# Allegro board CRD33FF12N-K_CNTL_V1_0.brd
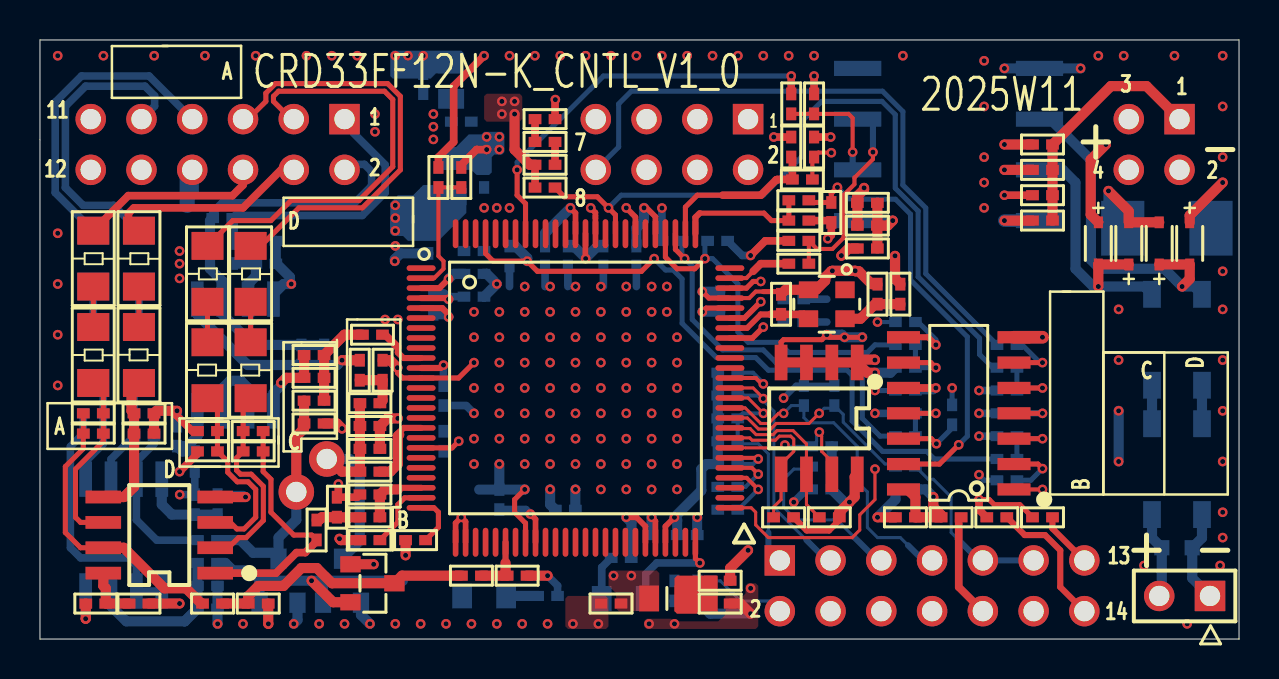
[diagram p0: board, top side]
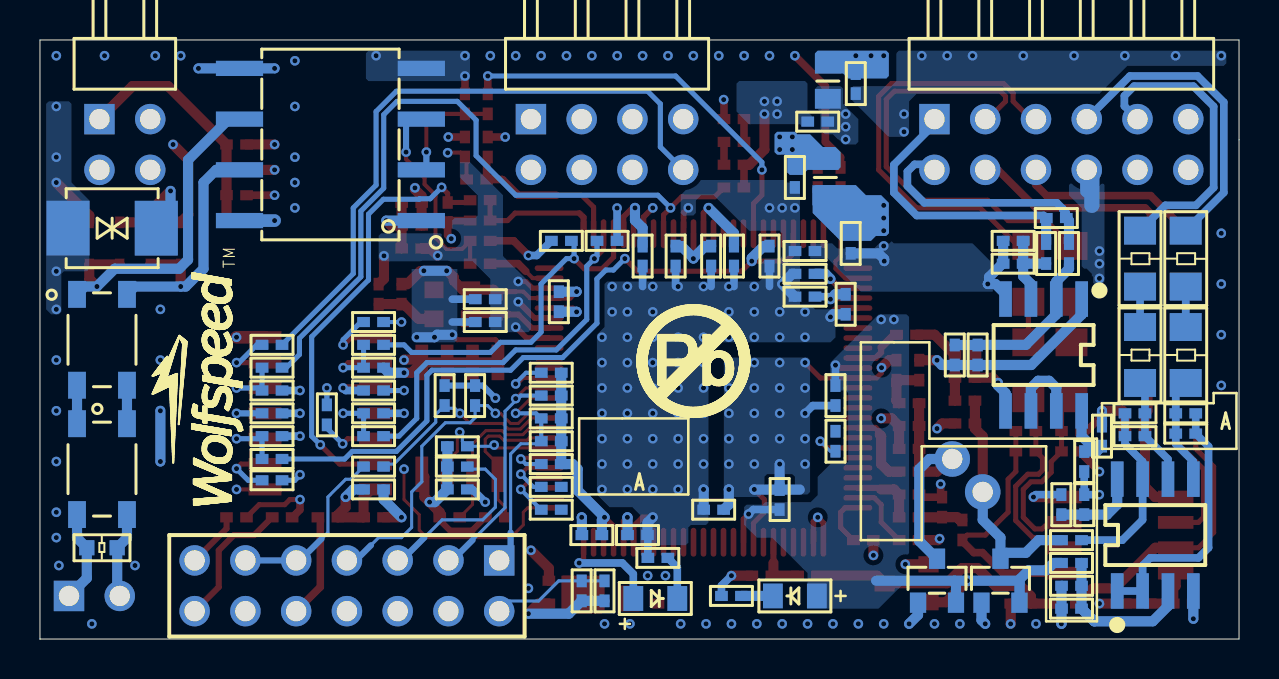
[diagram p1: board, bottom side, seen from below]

Outline 60 x 30 mm; copper layers: TOP, POWER02, GND03, BOTTOM. Coordinates in mm from the lower left corner of the outline.
Outline path: 0,30 60,30 60,0 0,0 0,30

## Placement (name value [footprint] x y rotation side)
C1  2.2u  [C0402]  37.72 17.02 180 bottom
C2  0.1u  [C0402]  32.89 2.41 90 bottom
C3  2.2u  [C0402]  41.91 17.27 90 top
C4  22p  [C0402]  37.08 16.76 90 top
C5  22n  [C0402]  19.94 23.11 90 top
C6  10u  [C0402]  26.42 19.18 90 bottom
C7  10u  [C0402]  21.72 17.14 180 bottom
C8  0.1u  [C0402]  28.19 19.18 90 bottom
C9  0.1u  [C0402]  34.04 16.89 270 bottom
C10  0.1u  [C0402]  30.1 5.21 0 bottom
C11  0.1u  [C0402]  19.68 16.76 90 bottom
C12  2.2u  [C0402]  20.19 12.19 270 bottom
C13  2.2u  [C0402]  22.99 6.99 90 bottom
C14  0.1u  [C0402]  21.72 18.29 0 bottom
C15  0.1u  [C0402]  32.38 5.21 0 bottom
C16  0.1u  [C0402]  37.72 15.88 0 bottom
C17  0.1u  [C0402]  25.27 19.18 270 bottom
C18  0.1u  [C0402]  29.84 19.18 270 bottom
C19  10u  [C0402]  19.43 19.81 270 bottom
C20  10u  [C0402]  22.23 23.11 270 bottom
C21  0.1n  [C0402]  39.6 21.36 270 top
C22  0.1n  [C0402]  38.73 24.64 90 top
C23  0.1u  [C0402]  39.12 7.49 180 bottom
C24  2.2n  [C0402]  16.51 7.24 180 top
C25  0.01u  [C0402]  14.22 14.22 90 bottom
C26  2.2n  [C0402]  17.14 13.46 90 top
C27  2.2n  [C0402]  10.67 10.41 180 top
C28  10u  [C0402]  28.57 1.78 180 top
C29  10u  [C0402]  34.04 1.78 0 top
C30  0.01u  [C0402]  11.3 18.8 180 bottom
C31  2.2n  [C0402]  14.86 6.6 90 top
C32  10u  [C0402]  19.18 27.81 270 bottom
C33  0.1u  [C0402]  21.08 25.91 0 bottom
C34  2.2n  [C0402]  10.92 1.78 0 top
C35  0.01u  [C0402]  50.16 22.23 180 top
C36  0.1u  [C0402]  50.16 23.5 180 top
C37  0.47u  [C0402]  8.38 1.52 0 bottom
C38  1u  [C0402]  50.16 24.77 180 top
C39  0.1u  [C0402]  41.4 20.7 0 top
C40  1u  [C0402]  41.4 21.84 0 top
C41  0.1u  [C0402]  8.89 6.73 90 bottom
C45  330p  [C0402]  2.67 10.29 0 bottom
C47  330p  [C0402]  5.21 11.3 0 bottom
C48  2.2n  [C0402]  13.72 10.79 0 top
C49  0.1u  [C0402]  2.79 1.78 180 top
C50  0.1u  [C0402]  6.86 10.16 90 bottom
C51  120p  [C0402]  38.73 26.8 90 top
C52  22n  [C0402]  8.38 9.4 0 top
C54  120p  [C0402]  25.27 23.75 0 top
C55  22n  [C0402]  5.21 10.29 180 top
C56  2.2n  [C0402]  2.67 10.29 0 top
C65  0.1n  [C0402]  43.31 13.59 180 bottom
C66  0.1n  [C0402]  43.31 11.3 180 bottom
C67  0.1n  [C0402]  48.39 10.16 180 bottom
C68  0.1n  [C0402]  48.39 12.45 180 bottom
C69  1u  [C0402]  45.59 6.1 0 top
C70  0.1u  [C0402]  43.31 6.1 180 top
C71  0.01u  [C0402]  43.31 7.49 180 bottom
C72  2.2n  [C0402]  16.51 10.67 0 top
C73  2.2n  [C0402]  13.72 14.22 180 top
C74  2.2n  [C0402]  23.88 3.17 0 top
C75  2.2u  [C0402]  16.51 4.95 180 top
C76  2.2u  [C0402]  18.8 4.95 180 top
C79  120p  [C0402]  37.97 19.94 180 top
D2  LED0  [LED0805]  29.21 2.03 180 bottom
D3  LED0  [LED0805]  22.23 2.16 0 bottom
D4  BAS21WS-TP  [DIOD-SOD323-2-A_V]  54.48 19.81 90 top
D5  BAS21WS-TP  [DIOD-SOD323-2-A_V]  56.01 19.81 90 top
D6  BAS21WS-TP  [DIOD-SOD323-2-A_V]  52.96 19.81 270 top
D7  BAS21WS-TP  [DIOD-SOD323-2-A_V]  57.53 19.81 270 top
D8  SMBJ15CA  [DO214AA]  56.39 20.57 0 bottom
D13  BAV99-TP  [SOT-23-3]  16.64 2.79 270 top
D14  BAV99-TP  [SOT-23-3]  11.94 2.92 180 bottom
D18  BAV99-TP  [SOT-23-3]  15.11 2.92 180 bottom
J1  Analog Singals  [HDR2X6H-254MM-90]  8.89 24.77 180 top
J2  Digital Singals  [HDR2X4H-254MM-90]  31.62 24.77 180 top
J3  JTAG  [HDR2X7H-254MM]  44.64 2.67 0 top
J4  CAN  [HDR1X2H-254MM]  57.28 2.16 180 top
J5  2*2P 1.27mm  [HDR2X2H-254MM-90]  55.75 24.77 180 top
L1  BLM21PG221SN1D  [6-0805_L]  20.7 23.11 90 bottom
L2  BLM21PG221SN1D  [6-0805_L]  31.37 2.03 0 top
L3  BLM21PG221SN1D  [6-0805_L]  20.57 27.94 270 bottom
M1  Test point  [1P]  12.83 7.37 0 top
M2  Test point  [1P]  14.35 9.02 180 bottom
NOREF  -  []  124.59 89.92 0 top
NOREF#2  -  []  124.71 120.02 0 top
NOREF#3  -  []  124.46 30.1 0 top
NOREF#4  -  []  60 0 90 top
NOREF#5  -  []  -5 2 0 top
NOREF#6  -  []  59.94 154.69 90 top
NOREF#7  -  []  124.59 59.94 0 top
NOREF#8  -  []  0 0 0 top
NOREF#9  -  []  0 0 90 top
NOREF#10  -  []  211.28 116.3 0 top
NOREF#11  -  []  407.95 59.5 0 top
R1  0  [R0402]  31.75 2.41 90 bottom
R2  10k  [R0402]  34.42 9.91 180 bottom
R3  10  [R0402]  43.05 17.27 270 top
R4  10k  [R0402]  34.42 12.19 180 bottom
R5  0  [R0402]  39.12 8.64 0 bottom
R6  10k  [R0402]  38.23 12.19 90 bottom
R7  10k  [R0402]  21.08 23.11 90 top
R8  10k  [R0402]  39.75 12.19 90 bottom
R9  2k  [R0402]  47.88 6.1 0 top
R10  0  [R0402]  43.31 8.64 180 bottom
R11  2k  [R0402]  50.16 6.1 0 top
R12  1k  [R0402]  45.64 11.23 270 bottom
R13  2k  [R0402]  29.08 4.06 180 bottom
R14  2k  [R0402]  25.4 2.16 180 bottom
R15  0  [R0402]  26.29 6.48 180 bottom
R16  1k  [R0402]  37.97 21.97 0 top
R17  1k  [R0402]  48.39 7.95 0 bottom
R18  1k  [R0402]  38.15 23.01 0 top
R19  2k  [R0402]  37.59 24.64 270 top
R20  2k  [R0402]  37.97 20.95 180 top
R21  0  [R0402]  21.72 19.43 0 bottom
R22  2k  [R0402]  8.38 3.81 180 bottom
R23  10  [R0402]  41.4 19.56 0 top
R24  2k  [R0402]  8.38 2.67 180 bottom
R25  10  [R0402]  7.75 6.73 90 bottom
R26  0  [R0402]  50.16 20.95 180 top
R27  1k  [R0402]  16.51 6.1 180 top
R28  1k  [R0402]  37.59 26.8 270 top
R29  1k  [R0402]  37.97 18.8 0 top
R30  12k  [R0402]  10.67 9.4 0 top
R31  120  [R0603]  56.9 4.57 0 bottom
R32  0  [R1206]  10.54 18.29 90 top
R33  10k  [R0402]  2.67 11.3 180 bottom
R34  620k  [R1206]  2.67 19.05 90 bottom
R35  10k  [R1206]  2.67 14.22 90 bottom
R36  12k  [R1206]  10.54 13.46 270 top
R37  620k  [R1206]  4.95 19.05 90 bottom
R38  10k  [R1206]  4.95 14.22 90 bottom
R39  10k  [R0402]  5.21 10.16 180 bottom
R40  1k  [R0402]  8.38 4.95 180 bottom
R41  10  [R0402]  4.95 1.78 0 top
R42  10  [R0402]  7.75 8.89 270 bottom
R43  100  [R0402]  34.42 6.48 0 bottom
R44  10k  [R0402]  25.27 26.04 180 top
R45  1k  [R0402]  13.84 5.46 90 top
R46  1k  [R0402]  8.64 1.78 0 top
R47  1k  [R0402]  25.27 24.89 0 top
R48  0  [R1206]  4.95 19.05 90 top
R49  12k  [R1206]  4.95 14.22 270 top
R50  0  [R1206]  8.38 18.29 90 top
R51  12k  [R0402]  5.21 11.3 0 top
R52  12k  [R0402]  2.67 11.3 180 top
R53  0  [R1206]  2.67 19.05 90 top
R54  12k  [R1206]  2.67 14.22 90 top
R55  12k  [R1206]  8.38 13.46 270 top
R57  12k  [R0402]  8.38 10.41 180 top
R65  100  [R0402]  34.42 7.62 0 bottom
R71  1k  [R0402]  43.31 15.88 0 bottom
R72  1k  [R0402]  48.39 14.73 0 bottom
R73  1k  [R0402]  43.31 14.73 0 bottom
R74  1k  [R0402]  48.39 13.59 0 bottom
R75  1k  [R0402]  43.31 12.45 0 bottom
R76  1k  [R0402]  43.31 10.16 0 bottom
R77  1k  [R0402]  48.39 11.3 0 bottom
R78  1k  [R0402]  48.39 9.02 0 bottom
R79  10  [R0402]  34.04 2.92 0 top
R80  2k  [R0402]  33.91 19.94 180 bottom
R81  2k  [R0402]  31.62 19.94 0 bottom
R82  2k  [R0402]  23.5 19.18 90 bottom
R83  2k  [R0402]  25.27 22.61 0 top
R85  1k  [R0402]  16.51 11.81 0 top
R86  1k  [R0402]  13.72 11.94 180 top
R87  NA  [R0402]  16.51 9.53 180 top
R88  100  [R0402]  16.64 15.24 180 top
R89  1k  [R0402]  21.59 3.17 180 top
R90  NA  [R0402]  13.72 13.08 0 top
R93  10k  [R0402]  37.21 6.1 0 top
R94  10k  [R0402]  39.5 6.1 0 top
R95  10k  [R0402]  39.12 9.65 0 bottom
R97  100  [R0402]  16.51 8.38 180 top
R100  100  [R0402]  20.19 9.91 90 bottom
R101  1k  [R0402]  16 13.46 90 top
R102  2k  [R0402]  13.08 14.22 270 bottom
R103  2k  [R0402]  8.51 19.3 270 bottom
R104  NA  [R0402]  9.14 21.08 180 bottom
R105  2k  [R0402]  9.65 19.3 270 bottom
R106  2k  [R0402]  11.3 19.94 0 bottom
R107  2k  [R0402]  34.42 11.05 180 bottom
R108  2k  [R0402]  34.42 13.34 180 bottom
R109  2k  [R0402]  34.42 8.76 180 bottom
T1  DLW43SH101XK2L  [FP-DLW43-0_2-T2_6-E0_6-MFG]  56.9 14.99 270 bottom
T2  DLW43SH101XK2L  [FP-DLW43-0_2-T2_6-E0_6-MFG]  56.9 8.51 270 bottom
U1  F280049CPZS  [PZ0100A_N]  26.8 12.57 0 top
U3  OPA2376AQDRQ1  [8SOIC]  4.19 5.21 90 bottom
U4  ISO1050DUBR  [8-SOP]  45.47 24.77 0 bottom
U7  OPA2376  [8SOIC]  5.97 5.21 180 top
U9  OPA2376AQDRQ1  [8SOIC]  9.78 14.22 270 bottom
U11  MC74VHCT50ADR2G  [14SOIC]  45.97 11.3 180 top
U12  24LC16BT-I/SN  [8SOIC]  38.99 11.05 270 top
Y1  OSC4_250*200  [TBD-FOOTPRINT-1]  39.37 16.76 180 top

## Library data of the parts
C1-C41 C45 C47-C52 C54-C56 C65-C76 C79 = C0402: Tolerance: #TOL; User Part Number: HAMP
D2 D3 = LED0805: User Part Number: HAMP; Tolerance: #TOL
D4-D7 = DIOD-SOD323-2-A_V: Tolerance: #TOL; User Part Number: HAMP
D8 = DO214AA: Tolerance: #TOL; User Part Number: HAMP
D13 D14 D18 = SOT-23-3: Tolerance: #TOL; User Part Number: HAMP
J1 = HDR2X6H-254MM-90: Tolerance: #TOL; User Part Number: HAMP
J2 = HDR2X4H-254MM-90: Tolerance: #TOL; User Part Number: HAMP
J3 = HDR2X7H-254MM: Tolerance: #TOL; User Part Number: HAMP
J4 = HDR1X2H-254MM: Tolerance: #TOL; User Part Number: HAMP
J5 = HDR2X2H-254MM-90: Tolerance: #TOL; User Part Number: HAMP
L1-L3 = 6-0805_L: Tolerance: #TOL; User Part Number: HAMP
M1 M2 = 1P: User Part Number: HAMP; Tolerance: #TOL
R1-R30 R33 R39-R47 R51 R52 R57 R65 R71-R83 R85-R90 R93-R95 R97 R100-R109 = R0402: Tolerance: #TOL; User Part Number: HAMP
R31 = R0603: Tolerance: #TOL; User Part Number: HAMP
R32 R34-R38 R48-R50 R53-R55 = R1206: Tolerance: #TOL; User Part Number: HAMP
T1 T2 = FP-DLW43-0_2-T2_6-E0_6-MFG: Tolerance: #TOL; User Part Number: HAMP
U1 = PZ0100A_N: Tolerance: #TOL; User Part Number: HAMP
U3 U7 U9 U12 = 8SOIC: Tolerance: #TOL; User Part Number: HAMP
U4 = 8-SOP: Tolerance: #TOL; User Part Number: HAMP
U11 = 14SOIC: Tolerance: #TOL; User Part Number: HAMP
Y1 = TBD-FOOTPRINT-1: Tolerance: #TOL; User Part Number: HAMP

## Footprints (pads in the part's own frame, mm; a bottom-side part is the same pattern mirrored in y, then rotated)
1P
  round 1.778 hole 1.016: 1(0,0)
6-0805_L
  rect 0.991x1.295 smd: 1(-0.889,0) 2(0.889,0)
8-SOP
  rect 2.362x0.762 smd: 1(-4.55,3.81) 2(-4.55,1.27) 3(-4.55,-1.27) 4(-4.55,-3.81) 5(4.55,-3.81) 6(4.55,-1.27) 7(4.55,1.27) 8(4.55,3.81)
8SOIC
  rect 1.778x0.635 smd: 1(-2.8,1.905) 2(-2.8,0.635) 3(-2.8,-0.635) 4(-2.8,-1.905) 5(2.8,-1.905) 6(2.8,-0.635) 7(2.8,0.635) 8(2.8,1.905)
14SOIC
  rect 1.651x0.61 smd: 1(-2.765,3.81) 2(-2.765,2.54) 3(-2.765,1.27) 4(-2.765,0) 5(-2.765,-1.27) 6(-2.765,-2.54) 7(-2.765,-3.81) 8(2.765,-3.81) 9(2.765,-2.54) 10(2.765,-1.27) 11(2.765,0) 12(2.765,1.27) 13(2.765,2.54) 14(2.765,3.81)
C0402
  rect 0.635x0.508 smd: 1(-0.5,0) 2(0.5,0)
DIOD-SOD323-2-A_V
  rect 0.584x0.457 smd: 1(-1.055,0) 2(1.055,0)
DO214AA
  rect 2.159x2.743 smd: 1(2.21,0) 2(-2.21,0)
FP-DLW43-0_2-T2_6-E0_6-MFG
  rect 1.346x0.889 smd: 1(-2.275,-1.25) 2(2.275,-1.25) 3(2.275,1.25) 4(-2.275,1.25)
HDR1X2H-254MM
  rect 1.524x1.524 hole 1.016: 1(-1.27,0)
  round 1.524 hole 1.016: 2(1.27,0)
HDR2X2H-254MM-90
  rect 1.524x1.524 hole 1.016: 1(-1.27,-1.27)
  round 1.524 hole 1.016: 2(-1.27,1.27) 3(1.27,-1.27) 4(1.27,1.27)
HDR2X4H-254MM-90
  rect 1.524x1.524 hole 1.016: 1(-3.81,-1.27)
  round 1.524 hole 1.016: 2(-3.81,1.27) 3(-1.27,-1.27) 4(-1.27,1.27) 5(1.27,-1.27) 6(1.27,1.27) 7(3.81,-1.27) 8(3.81,1.27)
HDR2X6H-254MM-90
  rect 1.524x1.524 hole 1.016: 1(-6.35,-1.27)
  round 1.524 hole 1.016: 2(-6.35,1.27) 3(-3.81,-1.27) 4(-3.81,1.27) 5(-1.27,-1.27) 6(-1.27,1.27) 7(1.27,-1.27) 8(1.27,1.27) 9(3.81,-1.27) 10(3.81,1.27) 11(6.35,-1.27) 12(6.35,1.27)
HDR2X7H-254MM
  rect 1.524x1.524 hole 1.016: 1(-7.62,1.27)
  round 1.524 hole 1.016: 2(-7.62,-1.27) 3(-5.08,1.27) 4(-5.08,-1.27) 5(-2.54,1.27) 6(-2.54,-1.27) 7(0,1.27) 8(0,-1.27) 9(2.54,1.27) 10(2.54,-1.27) 11(5.08,1.27) 12(5.08,-1.27) 13(7.62,1.27) 14(7.62,-1.27)
LED0805
  rect 0.991x1.245 smd: 1(-1.1,0) 2(1.1,0)
PZ0100A_N
  oval 1.448x0.279 smd: 1(-7.725,6) 2(-7.725,5.5) 3(-7.725,5) 4(-7.725,4.5) 5(-7.725,4) 6(-7.725,3.5) 7(-7.725,3) 8(-7.725,2.5) 9(-7.725,2) 10(-7.725,1.5) 11(-7.725,1) 12(-7.725,0.5) 13(-7.725,0) 14(-7.725,-0.5) 15(-7.725,-1) 16(-7.725,-1.5) 17(-7.725,-2) 18(-7.725,-2.5) 19(-7.725,-3) 20(-7.725,-3.5) 21(-7.725,-4) 22(-7.725,-4.5) 23(-7.725,-5) 24(-7.725,-5.5) 25(-7.725,-6) 51(7.725,-6) 52(7.725,-5.5) 53(7.725,-5) 54(7.725,-4.5) 55(7.725,-4) 56(7.725,-3.5) 57(7.725,-3) 58(7.725,-2.5) 59(7.725,-2) 60(7.725,-1.5) 61(7.725,-1) 62(7.725,-0.5) 63(7.725,0) 64(7.725,0.5) 65(7.725,1) 66(7.725,1.5) 67(7.725,2) 68(7.725,2.5) 69(7.725,3) 70(7.725,3.5) 71(7.725,4) 72(7.725,4.5) 73(7.725,5) 74(7.725,5.5) 75(7.725,6)
  oval 0.279x1.448 smd: 26(-6,-7.725) 27(-5.5,-7.725) 28(-5,-7.725) 29(-4.5,-7.725) 30(-4,-7.725) 31(-3.5,-7.725) 32(-3,-7.725) 33(-2.5,-7.725) 34(-2,-7.725) 35(-1.5,-7.725) 36(-1,-7.725) 37(-0.5,-7.725) 38(0,-7.725) 39(0.5,-7.725) 40(1,-7.725) 41(1.5,-7.725) 42(2,-7.725) 43(2.5,-7.725) 44(3,-7.725) 45(3.5,-7.725) 46(4,-7.725) 47(4.5,-7.725) 48(5,-7.725) 49(5.5,-7.725) 50(6,-7.725) 76(6,7.725) 77(5.5,7.725) 78(5,7.725) 79(4.5,7.725) 80(4,7.725) 81(3.5,7.725) 82(3,7.725) 83(2.5,7.725) 84(2,7.725) 85(1.5,7.725) 86(1,7.725) 87(0.5,7.725) 88(0,7.725) 89(-0.5,7.725) 90(-1,7.725) 91(-1.5,7.725) 92(-2,7.725) 93(-2.5,7.725) 94(-3,7.725) 95(-3.5,7.725) 96(-4,7.725) 97(-4.5,7.725) 98(-5,7.725) 99(-5.5,7.725) 100(-6,7.725)
R0402
  rect 0.635x0.508 smd: 1(-0.5,0) 2(0.5,0)
R0603
  rect 0.762x0.762 smd: 1(-0.76,0) 2(0.76,0)
R1206
  rect 1.397x1.6 smd: 1(-1.4,0) 2(1.4,0)
SOT-23-3
  rect 0.813x1.016 smd: 1(-0.95,-1.1) 2(0.95,-1.1) 3(0,1.1)
TBD-FOOTPRINT-1
  rect 0.965x0.838 smd: 1(-0.913,-0.725) 2(0.913,-0.725) 3(0.913,0.725) 4(-0.913,0.725)

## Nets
AGND: C12.2 C13.2 C19.2 C24.2 C26.2 C28.2 C30.1 C31.2 C32.2 C34.2 C37.2 C41.2 C48.2 C49.2 C50.2 C52.1 C55.1 C72.2 C73.2 C74.2 C75.2 C76.2 D13.1 D14.1 D18.1 J1.10 R14.1 R15.2 R21.1 R24.1 R51.2 R57.2 R87.1 R90.1 R106.2 U1.12 U1.26 U1.27 U1.33 U3.4 U7.4 U9.4 U9.5
DGND: C1.1 C2.1 C3.2 C4.2 C5.2 C6.1 C7.1 C8.1 C9.1 C10.1 C11.1 C14.2 C15.2 C16.2 C17.2 C18.2 C20.2 C21.2 C22.2 C23.2 C29.2 C33.2 C39.1 C40.1 C51.2 C54.1 C65.2 C66.2 C67.2 C68.2 C69.2 C70.2 C71.2 C79.2 J2.3 J3.4 J3.6 J3.8 J3.10 J3.12 R1.1 R13.1 R15.1 R19.1 R20.1 R21.2 R80.1 R81.1 R82.1 R83.1 U1.5 U1.45 U1.72 U1.82 U1.86 U4.4 U11.7 U12.1 U12.2 U12.3 U12.4 Y1.2
A_1.2V: C32.1 J1.11 L3.1
A_3.3V: C12.1 C13.1 C19.1 D3.1 D13.2 D14.2 D18.2 J1.12 L1.1 R22.1 U1.11 U1.34
CAN+: J4.2 J5.4 R31.1 T2.3
CAN+5V: C35.1 C36.1 C38.1 J5.1 R26.1
CAN-: J4.1 J5.2 R31.2 T2.2
CAN_GND: C35.2 C36.2 C38.2 D6.1 D7.1 D8.1 J5.3 U4.5
CANRX: R28.1 U1.93
CANTX: R29.1 U1.74
D_1.2V: C6.2 C7.2 C8.2 C9.2 C10.2 C11.2 C33.1 L3.2 U1.4 U1.46 U1.71 U1.87
D_3.3V: C1.2 C14.1 C15.1 C16.1 C17.1 C18.1 C20.1 C23.1 L1.2 R2.2 R3.1 R4.2 R5.2 R6.2 R7.2 R8.2 R9.1 R11.1 R23.1 R44.1 R93.2 R94.2 R95.2 R107.2 R108.2 R109.2 U1.3 U1.47 U1.68 U1.70 U1.73 U1.80 U1.88 U12.8
DC_H_+: J1.4 R48.2
DC_H_-: J1.6 R53.2
DC_L_+: J1.3 R50.2
DC_L_-: J1.5 R32.2
IL: C26.1 R85.2 R101.1
IL1: C72.1 D18.3 M2.1 R85.1 R87.2 R97.2
IL+: J1.1 R104.1 R105.1
IL-: J1.2 R103.1 R104.2
IOCP: R44.2 R47.1
IOCP1: C54.2 R47.2
LED_RED: D2.1 U1.50
MCU_X1: C4.1 U1.69 Y1.3
NETC3_1: C3.1 R3.2 Y1.4
NETC21_1: C21.1 R16.2 U11.13
NETC22_1: C22.1 R18.2 U11.1
NETC24_1: C24.1 R27.1 U1.23
NETC25_1: C25.1 R101.2 R102.2 U9.1
NETC25_2: C25.2 R102.1 R103.2 U9.2
NETC27_1: C27.1 R30.2 R45.1 U7.1
NETC27_2: C27.2 R30.1 R36.2 U7.2
NETC30_2: C30.2 R105.2 R106.1 U9.3
NETC37_1: C37.1 R22.2 R24.2 U3.3
NETC39_2: C39.2 C40.2 R23.2 U4.1
NETC41_1: C41.1 R25.1 U3.8
NETC45_2: C45.2 R33.1 R35.1 U3.5
NETC47_1: C47.1 R38.1 R39.2 U3.6
NETC47_2: C47.2 R39.1 R40.2 U3.7
NETC49_1: C49.1 R41.1 U7.8
NETC50_1: C50.1 R42.1 U9.8
NETC51_1: C51.1 R28.2 U4.2
NETC52_2: C52.2 R55.2 R57.1 U7.3
NETC55_2: C55.2 R49.2 R51.1 U7.5
NETC56_1: C56.1 R46.1 R52.2 U7.7
NETC56_2: C56.2 R52.1 R54.1 U7.6
NETC65_1: C65.1 R73.2 U11.9
NETC66_1: C66.1 R76.2 U11.11
NETC67_1: C67.1 R78.2 U11.3
NETC68_1: C68.1 R74.2 U11.5
NETC69_1: C69.1 C70.1 C71.1 R79.2 U11.14
NETC73_1: C73.1 R86.1 R88.2 R90.2
NETC74_1: C74.1 R89.1 U1.31
NETC75_1: C75.1 U1.24
NETC76_1: C76.1 U1.25
NETC79_1: C79.1 R29.2 U4.3
NETD2_2: D2.2 R13.2
NETD3_2: D3.2 R14.2
NETD4_1: D4.1 D6.2 T1.4 U4.7
NETD4_2: D4.2 D5.2 D8.2
NETD5_1: D5.1 D7.2 T1.1 U4.6
NETJ3_5: J3.5 R5.1
NETJ3_9: J3.9 J3.11 R10.1
NETJ3_13: J3.13 R11.2
NETJ3_14: J3.14 R9.2
NETR12_2: R12.2 U11.12
NETR17_2: R17.2 U11.2
NETR26_2: R26.2 U4.8
NETR32_1: R32.1 R36.1
NETR34_1: R34.1 R35.2
NETR37_1: R37.1 R38.2
NETR43_2: R43.2 U1.54
NETR48_1: R48.1 R49.1
NETR50_1: R50.1 R55.1
NETR53_1: R53.1 R54.2
NETR65_2: R65.2 U1.55
NETR71_2: R71.2 U11.8
NETR72_2: R72.2 U11.6
NETR75_2: R75.2 U11.10
NETR77_2: R77.2 U11.4
NETR88_1: R88.1 U1.10
NETR97_1: R97.1 U1.17
NETR100_1: R100.1 U1.19
NETR108_1: R108.1 U1.64
NETR109_1: R109.1 U1.56
NETT1_2: T1.2 T2.1
NETT1_3: T1.3 T2.4
NETU9_6: U9.6 U9.7
PWM-1A: J2.2 R71.1
PWM-1AA: R73.1 R80.2 U1.79
PWM-1B: J2.4 R75.1
PWM-1BB: R76.1 R81.2 U1.78
PWM-2A: J2.6 R77.1
PWM-2AA: R78.1 R82.2 U1.97
PWM-2B: J2.8 R72.1
PWM-2BB: R74.1 R83.2 U1.84
PWM-3A: J2.5 R17.1
PWM-3AA: R18.1 R19.2 U1.77
PWM-3B: J2.7 R12.1
PWM-3BB: R16.1 R20.2 U1.76
REF1.65: C45.1 R33.2 U3.1 U3.2
RELAY: J2.1 U1.51
SCL: R94.1 U1.59 U12.6
SDA: R93.1 U1.58 U12.5
TCK_P: R8.1 R10.2 U1.60
TDI_P: J3.3 R4.1 U1.63
TDO_P: J3.7 R6.1 U1.61
TMS_P: J3.1 R2.1 R107.1 U1.62
TRST_P: C2.2 J3.2 R1.2
VA+5V: C28.1 J1.8 L2.1 R25.2 R41.2 R42.2
VAC: C48.1 D14.3 M1.1 R40.1 R86.2
VD+5V: C29.1 L2.2 R79.1
VDC_L: C31.1 R27.2 R45.2
VDC_U: C34.1 D13.3 R46.2 R89.2
VL: J1.7 R34.2
VN: J1.9 R37.2
WP: R95.1 U1.57 U12.7
XRS: C5.1 R7.1 U1.2

Pads without a net: R43 1; R65 1; R100 2; U1 1 6 7 8 9 13 14 15 16 18 20 21 22 28 29 30 32 35 36 37 38 39 40 41 42 43 44 48 49 52 53 65 66 67 75 81 83 85 89 90 91 92 94 95 96 98 99 100; Y1 1

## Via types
v1: diameter 0.483, hole 0.254, TOP to BOTTOM, 300 vias

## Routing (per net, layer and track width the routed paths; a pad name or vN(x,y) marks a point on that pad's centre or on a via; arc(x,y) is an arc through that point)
AGND: length 58.3
  TOP w0.254: v1(21.72,13.84) 20.95,13.07 U1.12 18.14,13.07 17.89,13.33 v1(17.89,13.59) ; U1.33 24.3,5.8 23.75,6.35 23.75,6.99 v1(24.26,7.49)
  TOP w0.279: U1.26 20.8,5.81 v1(21.08,6.1) 21.3,5.88 U1.27
  TOP w0.381: v1(6.86,11.43) 6.86,11.18 7.62,10.41 R57.2 ; C52.1 7.88,9.28 v1(6.99,8.38) ; v1(14.93,7.76) 14.93,7.18 C31.2 15.88,7.1 C24.2
  TOP w0.508: C76.2 v1(18.3,4.19) ; v1(17.89,13.59) 17.52,13.96 C26.2 ; v1(11.43,0.76) 11.42,0.77 C34.2 ; U7.4 v1(10.29,7.11) ; v1(12.06,12.83) 12.32,13.08 R90.1 C73.2 ; C55.1 R51.2 5.83,11.43 v1(6.86,11.43) ; C75.2 15.06,4.95 v1(14.99,5.02) ; v1(17.91,11.05) 17.39,11.05 C72.2 R87.1 ; v1(2.29,1.02) 2.29,1.02 C49.2 ; C74.2 v1(25.4,3.17) ; D13.1 v1(16.7,3.74) ; C48.2 14.86,10.79 v1(15.11,10.54)
  POWER02 w0.66: J1.10 5.08,24.56 ; J1.10 5.08,22.43 ; J1.10 4.01,23.5 ; J1.10 6.15,23.5
  BOTTOM w0.381: v1(10.29,7.11) 10.17,7.23 C41.2 ; C12.2 21.33,11.69 v1(21.72,11.3) ; R14.1 25.9,2.67 v1(25.4,3.17)
  BOTTOM w0.508: v1(12.7,0.76) 12.89,0.95 D14.1 ; C13.2 21.98,7.49 ; C13.2 v1(22.99,8.76) ; C13.2 24.25,7.49 v1(24.26,7.49) ; v1(8.89,0.76) 8.88,0.77 C37.2 R24.1 ; U9.4 11.68,17.27 12.19,17.78 v1(12.57,17.78) 12.51,17.84 12.51,18.12 11.84,18.8 C30.1 R106.2 ; v1(12.06,12.83) 12.06,12.7 11.68,12.32 U9.5 ; v1(17.75,18.92) 17.75,19.02 18.04,19.31 C19.2 ; R15.2 25.53,6.74 25.53,7.49 v1(25.53,7.49) ; U3.4 v1(2.29,1.02) ; v1(16.51,0.76) 16.06,1.21 D18.1 ; C50.2 v1(6.86,11.43)
  vias: v1(0.89,29.21) v1(0.89,20.32) v1(0.89,17.78) v1(0.89,15.24) v1(0.89,12.7) v1(3.17,29.21) v1(5.71,29.21) v1(8.26,29.21) v1(10.16,0.76) v1(10.79,29.21) v1(13.34,29.21) v1(13.97,0.76) v1(14.61,29.21) v1(15.24,0.76) v1(15.88,29.21) v1(16.76,26.29) v1(16.76,25.4) v1(17.78,19.68) v1(17.78,0.76) v1(19.05,0.76) v1(20.32,0.76) v1(21.59,0.76) v1(21.72,12.57) v1(21.72,10.03) v1(21.72,8.76) v1(22.86,0.76) v1(22.99,13.84) v1(22.99,12.57) v1(22.99,11.3) v1(22.99,10.03) v1(24.13,0.76) v1(24.26,13.84) v1(24.26,12.57) v1(24.26,11.3) v1(24.26,10.03) v1(24.26,8.76) v1(25.4,0.76) v1(25.53,13.84) v1(25.53,12.57) v1(25.53,11.3) v1(25.53,10.03) v1(25.53,8.76) v1(26.67,0.76) v1(27.94,0.76)
DGND: length 122.2
  TOP w0.203: 36.2,17.4 35.81,17.4 35.49,17.07 U1.72
  TOP w0.254: U12.4 37.08,14.87 37.21,14.99 39.12,14.99 v1(39.37,15.24) 39.5,15.11 v1(40.26,15.11) v1(41.15,15.11) ; 36.2,17.4 36.95,17.4 C4.2 ; v1(33.15,17.4) 33.47,17.07 U1.72
  TOP w0.279: v1(27.56,21.59) 27.79,21.35 27.79,21.19 27.79,21.08 U1.86 ; U1.82 29.8,21.13 v1(29.34,21.59) ; v1(29.34,6.1) 29.84,6.1 30.3,5.64 U1.45
  TOP w0.305: v1(20.45,16.13) 20.45,16.26 20.13,16.57 U1.5
  TOP w0.381: J3.10 45.97,2.6 45.97,5.98 C69.2 ; C22.2 v1(39.57,25.14) ; C51.2 v1(38.73,28.19) ; R20.1 39.5,20.95 C21.2 39.6,20.23 v1(39.42,20.05) ; R83.1 C54.1 ; C5.2 19.94,24.13 20.7,24.89 20.7,27.69 v1(22.23,29.21) ; C79.2 36.29,19.94 v1(35.56,19.21) ; R19.1 v1(36.72,25.14)
  TOP w0.508: U12.1 U12.2 U12.3 U12.4 ; U12.1 40.89,13.84 41.4,13.34 v1(41.78,13.34) ; U12.1 41.04,13.99 41.76,13.99 v1(41.78,13.97) ; C70.2 v1(41.91,6.1) ; C39.1 C40.1 40.9,22.18 41.24,22.52 v1(41.24,22.59) ; v1(23.75,26.29) 23.75,24.51 24.51,23.75 C54.1 ; C29.2 35.05,1.78 v1(35.56,1.27) ; C3.2 41.62,17.77 40.98,18.42 40.82,18.42 v1(40.79,18.44) v1(39.65,18.44) 39.63,18.42 39.59,18.42 39.29,18.12 39.29,17.94 38.84,17.49 Y1.2 37.31,17.49 C4.2
  TOP w0.635: 48.74,15.11 v1(50.16,15.11)
  POWER02 w0.66: 43.57,1.4 J3.8 ; J3.8 45.71,1.4 ; J3.8 44.64,2.46 ; 49.72,2.46 J3.12 48.65,1.4 ; 31.83,26.04 J2.3 ; J2.3 33.96,26.04 ; J2.3 32.89,24.97 ; J2.3 32.89,27.1 ; 41.03,1.4 J3.6 ; J3.6 42.1,2.46 ; J3.6 43.17,1.4 ; J3.4 39.56,2.46 ; J3.4 38.49,1.4 ; J3.4 40.63,1.4 ; J3.10 48.25,1.4 ; J3.10 47.18,2.46 ; J3.10 46.11,1.4
  GND03 w0.66: 38.49,1.4 J3.4 ; J3.4 39.56,2.46 ; J3.4 40.63,1.4 ; J3.8 44.64,2.46 ; J3.8 43.57,1.4 ; J3.8 45.71,1.4 ; J3.6 42.1,2.46 ; J3.6 43.17,1.4 ; J3.6 41.03,1.4 ; J3.10 47.18,2.46 ; J3.10 46.11,1.4 ; J3.10 48.25,1.4 ; 49.72,2.46 J3.12 48.65,1.4
  BOTTOM w0.381: R80.1 35.14,19.21 v1(35.56,19.21) ; R13.1 29.58,5.19 C10.1 ; C16.2 39.37,15.88 ; v1(22.86,17.78) 22.73,17.91 ; C18.2 29.84,17.65 ; R81.1 v1(31.12,21.58) ; C17.2 25.27,17.65 ; C67.2 v1(46.99,10.16) ; C66.2 v1(41.78,11.3) ; R82.1 23.5,17.65 ; C6.1 26.42,17.65 ; C1.1 39.37,17.02 ; C8.1 28.19,17.65 ; C68.2 v1(46.99,12.45) ; C23.2 38.35,7.49 v1(37.72,6.86)
  BOTTOM w0.508: C10.1 29.6,5.83 v1(29.34,6.1) ; R1.1 C2.1 33.54,1.27 v1(35.56,1.27) ; C71.2 42.81,6.99 v1(41.91,6.1) ; v1(32.89,6.1) 32.89,6.09 C15.2 ; C65.2 42.55,13.34 v1(41.78,13.34) ; v1(20.45,16.13) 20.31,16.26 C11.1 ; v1(41.15,15.11) v1(40.26,15.11) 40.13,15.24 v1(39.37,15.24) ; v1(33.15,17.4) 33.15,17.39 C9.1 ; v1(26.8,7.49) 26.79,7.49 R15.1 ; C14.2 22.35,18.29 22.73,17.91 ; C7.1 22.23,17.14 v1(22.86,17.78) ; v1(39.65,18.44) v1(40.79,18.44)
  vias: v1(21.72,16.38) v1(21.72,15.11) v1(22.23,21.59) v1(22.86,21.59) v1(22.99,16.38) v1(22.99,15.11) v1(23.11,26.92) v1(23.11,26.29) v1(23.5,29.21) v1(23.5,21.59) v1(23.75,26.92) v1(24.26,17.65) v1(24.26,16.38) v1(24.26,15.11) v1(24.77,29.21) v1(25.53,17.65) v1(25.53,16.38) v1(25.53,15.11) v1(26.04,29.21) v1(26.8,17.65) v1(26.8,16.38) v1(26.8,15.11) v1(26.8,13.84) v1(26.8,12.57) v1(26.8,11.3) v1(26.8,10.03) v1(26.8,8.76) v1(27.3,29.21) v1(28.07,17.65) v1(28.07,16.38) v1(28.07,15.11) v1(28.07,13.84) v1(28.07,12.57) v1(28.07,11.3) v1(28.07,10.03) v1(28.07,8.76) v1(28.07,7.49) v1(28.57,29.21) v1(29.34,17.65) v1(29.34,16.38) v1(29.34,15.11) v1(29.34,13.84) v1(29.34,12.57) v1(29.34,11.3) v1(29.34,10.03) v1(29.34,8.76) v1(29.34,7.49) v1(29.84,29.21) v1(30.48,0.76) v1(30.61,17.65) v1(30.61,16.38) v1(30.61,15.11) v1(30.61,13.84) v1(30.61,12.57) v1(30.61,11.3) v1(30.61,10.03) v1(30.61,8.76) v1(30.61,7.49) v1(31.11,29.21) v1(31.37,17.65) v1(31.37,16.38) v1(31.75,0.76) v1(31.88,15.11) v1(31.88,13.84) v1(31.88,12.57) v1(31.88,11.3) v1(31.88,10.03) v1(31.88,8.76) v1(31.88,7.49) v1(32.38,29.21) v1(33.66,29.21) v1(34.92,29.21) v1(35.56,2.54) v1(36.2,29.21) v1(37.47,29.21) v1(38.73,29.21) v1(43.18,29.21)
A_1.2V: length 18
  GND03 w1.016: 17.78,27.94 4.45,27.94 J1.11
  BOTTOM w0.381: C32.1 19.18,28.45 ; 19.18,28.45 v1(18.41,29.21) ; 19.18,28.45 v1(19.18,29.21)
  vias: v1(17.78,29.21)
A_3.3V: length 25.2
  TOP w0.279: U1.34 24.8,6 v1(24.54,6.26)
  TOP w0.305: U1.11 20.05,13.57 v1(20.19,13.72)
  TOP w0.508: v1(13.59,2.92) 14.67,1.84 D13.2
  GND03 w0.66: 3.61,23.5 J1.12 2.54,22.43
  BOTTOM w0.381: v1(24.54,6.26) 24.31,6.48 C13.1 ; C12.1 v1(20.19,13.72) ; 10.99,2.86 10.92,2.79 10.92,1.89 D14.2
  BOTTOM w0.508: C19.1 19.3,20.45 v1(17.78,20.45) v1(17.78,21.08) ; 14.22,2.92 18.16,2.92 ; 14.22,2.92 14.16,2.86 D18.2 ; 14.22,2.92 v1(13.59,2.92) 11.05,2.92 ; D14.2 10.99,2.86 11.05,2.92 ; 11.05,2.92 10.53,3.44 9.65,3.44 9.28,3.81 R22.1
  vias: v1(17.27,16) v1(17.78,21.72) v1(17.91,16)
CAN+: length 26.9
  GND03 w0.508: J4.2 56.77,2.92 56.77,5.46 55.5,6.73 55.5,22.48 J5.4
  BOTTOM w0.508: J4.2 56.14,2.29 R31.1 55.65,5.06 T2.3
CAN+5V: length 12.1
  TOP w0.508: R26.1 C35.1 C36.1 C38.1 53.59,27.69 55.37,27.69 J5.1
CAN-: length 27.1
  GND03 w0.508: J5.2 56.39,22.86 56.39,7.11 57.66,5.84 57.66,3.05 J4.1
  BOTTOM w0.508: T2.2 58.15,5.06 R31.2 57.66,3.05 J4.1
CAN_GND: length 24
  TOP w0.381: C35.2 v1(48.26,22.23)
  TOP w0.508: v1(59.18,22.86) 57.53,21.21 D7.1 ; D6.1 52.58,21.25 52.58,24 v1(53.34,24.77) ; C38.2 v1(48.26,24.77) ; C36.2 v1(48.26,23.5)
  POWER02 w0.66: 54.48,24.97 J5.3 ; J5.3 54.48,27.1 ; J5.3 53.42,26.04
  GND03 w0.66: 54.48,24.97 J5.3 ; J5.3 54.48,27.1 ; J5.3 53.42,26.04
  BOTTOM w0.508: v1(53.98,8.89) v1(53.98,11.43) ; v1(48.26,28.57) U4.5 v1(52.07,28.57)
  vias: v1(47.24,28.96) v1(47.24,26.67) v1(47.24,24.13) v1(47.24,22.86) v1(47.24,21.59) v1(52.96,29.21) v1(53.98,16.51) v1(53.98,13.97) v1(54.23,29.21) v1(55.24,3.68) v1(56.77,29.21) v1(57.4,0.76) v1(59.05,3.68) v1(59.18,29.21) v1(59.18,26.67) v1(59.18,24.13) v1(59.18,18.41) v1(59.18,16.51) v1(59.18,13.97) v1(59.18,11.43) v1(59.18,8.89) v1(59.18,6.35) v1(59.18,5.08)
CANRX: length 20.2
  TOP w0.254: v1(23.88,23.5) 23.88,22.23 24.3,21.8 U1.93
  TOP w0.381: R28.1 v1(37.59,28.19)
  BOTTOM w0.254: v1(37.59,28.19) 28.19,28.19 23.88,23.88 v1(23.88,23.5)
CANTX: length 3.3
  TOP w0.203: 35.69,18.41 35.35,18.07 U1.74
  TOP w0.381: R29.1 36.07,18.8 35.69,18.41
D_1.2V: length 11.2
  TOP w0.254: 27.3,19.06 v1(27.3,19.05) ; v1(33.15,16.38) 33.34,16.57 U1.71
  TOP w0.279: U1.87 27.3,19.06 ; v1(30.61,6.1) 30.8,5.91 U1.46
  TOP w0.305: v1(20.45,17.02) 20.39,17.07 U1.4
  BOTTOM w0.381: C7.2 20.57,17.14 v1(20.45,17.02)
  BOTTOM w0.508: 27.3,19.08 v1(27.3,19.05) ; 27.3,19.08 27.9,19.68 C8.2 ; 27.3,19.08 26.71,19.68 C6.2 ; v1(33.15,16.38) 33.15,16.39 C9.2 ; C11.2 20.2,17.26 v1(20.45,17.02) ; v1(30.61,6.1) 30.6,6.09 C10.2
  vias: v1(19.68,26.29) v1(19.68,25.65) v1(19.68,25.02)
D_3.3V: length 47.1
  TOP w0.254: U1.73 35.35,17.57 35.69,17.91 v1(36.07,17.91) ; v1(46.99,6.99) 47.5,6.99 47.75,6.73 49.03,6.73 R11.1
  TOP w0.279: U1.68 35.65,15.07 v1(36.2,15.62) ; v1(31.75,6.1) 31.3,5.64 U1.47 ; U1.80 30.8,21.15 30.35,21.59 v1(30.23,21.59) ; v1(26.54,21.59) 26.8,21.34 U1.88 ; U1.70 35.25,16.07 v1(36.07,16.89)
  TOP w0.305: v1(20.45,18.03) 19.99,17.57 U1.3 ; R93.2 38.37,5.44 39.48,5.44 40,5.95 R94.2
  TOP w0.381: v1(22.35,24.51) 21.84,24.51 21.08,23.75 R7.2 ; v1(25.79,27.01) 25.77,27 R44.1 ; R9.1 47.37,6.1 46.99,6.48 v1(46.99,6.99)
  TOP w0.508: R94.2 40,6.35 v1(40.51,6.86) 40.77,7.12 40.77,8.12 U12.8 ; R23.1 40.46,19.56 40.11,19.2 v1(40.1,19.2) ; v1(42.79,19.19) 42.79,18.04 R3.1
  BOTTOM w0.305: v1(37.21,12.06) 37.84,12.69 R6.2 R8.2
  BOTTOM w0.508: v1(20.45,18.03) 20.7,18.29 C14.1 ; v1(40.51,6.86) 40.25,6.86 C23.1 R5.2 R95.2 ; R108.2 R4.2 R107.2 R2.2 R109.2 33.35,8.76 33.09,8.51 33.09,7.44 v1(31.75,6.1) 31.88,5.96 C15.1 ; C17.1 25.27,20.32 v1(26.54,21.59) ; v1(30.23,21.59) 30.23,20.97 29.84,20.59 C18.1
  vias: v1(22.35,25.15) v1(22.99,25.15) v1(22.99,24.51)
DC_H_+: length 10.4
  TOP w0.381: J1.4 12.06,23.5 10.16,21.59 4.7,21.59 4.43,21.32 4.43,20.78 4.76,20.45 R48.2
DC_H_-: length 9.2
  TOP w0.381: J1.6 10.16,22.73 9.63,22.2 4.42,22.2 R53.2
DC_L_+: length 22.2
  TOP w0.254: J1.3 12.57,26.04 11.68,26.92 11.68,27.18 11.94,27.43 17.24,27.43 17.65,27.02 17.65,23.65 15.97,21.97 12.57,21.97 11.56,20.95 9.65,20.95 R50.2
DC_L_-: length 21.9
  TOP w0.254: R32.2 11.05,19.69 12.95,21.59 16.13,21.59 18.03,23.5 18.03,27.18 17.4,27.81 11.78,27.81 11.3,27.34 11.3,26.92 10.41,26.04 J1.5
IL: length 2.3
  TOP w0.508: R85.2 17.14,11.95 C26.1 R101.1
IL1: length 12.1
  TOP w0.508: M2.1 14.48,9.02 15.11,8.38 R97.2 R87.2 C72.1 R85.1
  BOTTOM w0.508: D18.3 16,4.91 16,8.51 15.49,9.02 M2.1
IL+: length 14
  BOTTOM w0.381: R104.1 9.77,21.21 16.13,21.21 17.27,22.35 17.27,23.75 15.24,25.78 J1.1
  BOTTOM w0.508: R104.1 9.65,21.07 R105.1
IL-: length 12.5
  BOTTOM w0.381: J1.2 15.52,23.77 16.23,23.77 16.59,23.41 16.59,22.69 15.75,21.84 9.12,21.84 8.82,21.55 8.82,21.52 8.79,21.49 8.79,21.48 8.64,21.34 R104.2
  BOTTOM w0.508: R104.2 8.51,20.95 R103.1
IOCP: length 1.1
  TOP w0.381: R47.1 R44.2
IOCP1: length 1.1
  TOP w0.381: C54.2 R47.2
LED_RED: length 5.3
  TOP w0.254: U1.50 32.8,4.03 v1(33.02,3.81)
  BOTTOM w0.381: v1(33.02,3.81) 30.86,3.81 30.31,3.26 D2.1
MCU_X1: length 4.8
  TOP w0.279: 36.07,16.26 35.38,15.57 U1.69
  TOP w0.305: 36.07,16.26 37.09,16.26
  TOP w0.381: Y1.3 38.24,16.26 37.09,16.26 C4.1 36.58,16.26 36.58,16.26
NETC3_1: length 3.1
  TOP w0.508: R3.2 C3.1 41.79,16.77 41.06,16.04 Y1.4
NETC21_1: length 22.3
  TOP w0.254: U11.13 45.01,8.76 v1(45.97,9.73) ; v1(39.9,22.62) 39.6,22.31 C21.1 38.58,21.86 R16.2
  BOTTOM w0.254: v1(39.9,22.62) 40.47,22.05 41.01,22.05 41.03,22.02 42.81,22.02 43.56,21.27 43.56,17.98 46.41,15.14 46.41,10.16 v1(45.97,9.73)
NETC22_1: length 26.5
  TOP w0.203: U11.1 v1(50.16,7.49) ; v1(39.6,24.35) 39.59,24.36 38.96,24.36 C22.1 38.65,24.05 R18.2
  GND03 w0.254: v1(50.16,7.49) 49.53,7.49 48.54,8.48 48.54,12.97 45.86,15.65 43.97,15.65 42.04,17.58 42.04,19.74 39.37,22.4 39.37,24.12 v1(39.6,24.35)
NETC24_1: length 3.3
  TOP w0.305: 17.91,7.49 17.99,7.57 U1.23
  TOP w0.508: R27.1 C24.1 17.26,7.49 17.91,7.49
NETC25_1: length 10
  TOP w0.508: R101.2 v1(15.11,13.96)
  BOTTOM w0.508: U9.1 7.87,16.25 10.4,13.72 R102.2 C25.1 14.87,13.72 v1(15.11,13.96)
NETC25_2: length 8.5
  BOTTOM w0.508: R103.2 8.51,18.54 9.14,17.91 U9.2 9.14,16.26 10.67,14.73 13.07,14.73 R102.1 C25.2
NETC27_1: length 12.9
  TOP w0.254: R45.1 13.6,5.21 12.7,5.21 11.56,6.35 11.56,8 11.17,8.39 R30.2 C27.1
  TOP w0.381: U7.1 11.81,3.3 12.84,4.33 13.27,4.33 13.84,4.9 R45.1
NETC27_2: length 10.3
  TOP w0.254: R36.2 10.54,11.93 10.17,11.56 C27.2 R30.1 9.84,9.07 9.84,8.45 10.03,8.26 10.57,8.26 11.18,7.65 11.18,5.94 10.32,5.08 9.94,5.08 9.43,4.57 U7.2
NETC30_2: length 4.2
  BOTTOM w0.508: C30.2 9.66,18.8 R105.2 ; C30.2 R106.1 ; C30.2 10.8,18.17 10.41,17.78 U9.3
NETC37_1: length 8.9
  BOTTOM w0.508: 7.24,0.89 7.87,1.52 C37.1 ; 7.24,0.89 7.25,0.89 C37.1 ; 7.24,0.89 4.32,0.89 3.56,1.65 U3.3 ; C37.1 R24.2 R22.2
NETC39_2: length 4.9
  TOP w0.508: v1(42.67,20.95) 42.42,20.7 C39.2 ; C39.2 R23.2 ; C39.2 C40.2
  BOTTOM w0.508: U4.1 v1(42.67,20.95)
NETC41_1: length 4.3
  BOTTOM w0.508: U3.8 6.1,6.74 6.6,6.23 R25.1 C41.1
NETC45_2: length 5.4
  BOTTOM w0.381: U3.5 2.29,8.89 3.17,9.77 C45.2 R33.1 3.17,12.32 R35.1
NETC47_1: length 5.4
  BOTTOM w0.381: R38.1 4.71,12.58 C47.1 R39.2 3.56,9.01 U3.6
NETC47_2: length 9.2
  BOTTOM w0.381: R40.2 5.84,4.95 4.83,5.97 U3.7 4.83,8.89 5.71,9.77 R39.1 C47.2
NETC49_1: length 2.7
  TOP w0.508: U7.8 3.17,2.67 3.29,2.54 C49.1 R41.1
NETC50_1: length 3.5
  BOTTOM w0.508: R42.1 7.13,9.39 C50.1 7.37,9.66 7.88,10.17 7.88,11.42 U9.8
NETC51_1: length 5.9
  TOP w0.203: v1(40.67,24.38) 40.67,26.09 40.46,26.3 C51.1 R28.2
  BOTTOM w0.305: v1(40.67,24.38) 40.67,23.75 U4.2
NETC52_2: length 9.7
  TOP w0.254: U7.3 9.53,5.84 9.85,5.51 10.21,5.51 10.79,6.1 10.79,7.49 10.41,7.87 9.88,7.87 9.4,8.35 9.4,8.88 C52.2 R57.1 8.88,11.43 8.38,11.93 R55.2
NETC55_2: length 7.2
  TOP w0.508: R49.2 4.58,12.45 4.58,11.43 R51.1 C55.2 4.71,7.62 4.2,7.11 U7.5
NETC56_1: length 14.7
  TOP w0.254: R52.2 C56.1 2.17,9.53 1.27,8.64 1.27,5.33 2.03,4.57 U7.7
  TOP w0.508: U7.7 4.19,4.57 6.22,2.54 7.31,2.54 8.07,1.78 R46.1
NETC56_2: length 9
  TOP w0.254: R54.1 3.17,12.32 R52.1 C56.2 3.17,9.9 1.78,8.51 1.78,6.1 2.03,5.84 U7.6
NETC65_1: length 3.9
  TOP w0.254: v1(44.83,13.59) 44.58,13.84 U11.9
  BOTTOM w0.254: R73.2 C65.1 v1(44.83,13.59)
NETC66_1: length 3.8
  TOP w0.254: U11.11 v1(44.83,11.3)
  BOTTOM w0.254: R76.2 C66.1 v1(44.83,11.3)
NETC67_1: length 3.9
  TOP w0.254: 48.74,10.03 v1(50.16,10.03)
  BOTTOM w0.254: v1(50.16,10.03) 49.01,10.03 C67.1 R78.2
NETC68_1: length 3.9
  TOP w0.254: U11.5 v1(50.16,12.57)
  BOTTOM w0.254: R74.2 C68.1 49.01,12.57 v1(50.16,12.57)
NETC69_1: length 17.7
  TOP w0.508: v1(35.43,4.45) 34.54,3.55 R79.2 ; U11.14 43.42,7.49 43.81,7.1 C70.1 C69.1 45.09,6.22 44.7,6.6 v1(44.7,7.11)
  GND03 w0.508: v1(44.7,7.11) 42.93,5.33 36.07,5.33 35.43,4.7 v1(35.43,4.45)
  BOTTOM w0.508: C71.1 44.32,7.49 v1(44.7,7.11)
NETC73_1: length 4.6
  TOP w0.508: R88.2 15.23,15.24 C73.1 R90.2 R86.1
NETC74_1: length 3.2
  TOP w0.305: 23.12,3.17 23.3,3.36 ; 23.3,3.81 U1.31
  TOP w0.508: R89.1 C74.1 23.3,3.25 23.3,3.81
NETC75_1: length 3.5
  TOP w0.254: C75.1 17.91,5.85 17.91,6.73 18.25,7.07 U1.24
NETC76_1: length 2.6
  TOP w0.254: C76.1 19.94,5.6 19.94,6.35 19.72,6.57 U1.25
NETC79_1: length 10.4
  TOP w0.203: v1(41.68,24.38) 41.68,24.03 40.75,23.1 40.75,22.77 40.23,22.25 40.23,22.19 40.21,22.17 40.21,20.09 39.65,19.53 38.88,19.53 C79.1 R29.2
  BOTTOM w0.305: v1(41.68,24.38) 41.68,25.73 41.38,26.04 U4.3
NETD2_2: length 2.2
  BOTTOM w0.381: R13.2 28.11,3.59 D2.2
NETD3_2: length 1.6
  BOTTOM w0.508: R14.2 D3.2
NETD4_1: length 13.4
  TOP w0.508: D4.1 D6.2 v1(52.96,17.65)
  BOTTOM w0.508: U4.7 51.18,23.5 51.82,22.86 51.82,18.54 52.7,17.65 v1(52.96,17.65) 55.25,17.65 T1.4
NETD4_2: length 5.7
  TOP w0.508: v1(53.47,22.44) 54.48,21.42 D4.2 D5.2
  BOTTOM w0.508: D8.2 53.47,21.28 v1(53.47,22.44)
NETD5_1: length 17.5
  TOP w0.508: D5.1 D7.2 57.53,18.03 v1(57.15,17.65)
  BOTTOM w0.508: T1.1 57.75,17.65 v1(57.15,17.65) 56.26,18.54 53.04,18.54 52.59,18.99 52.59,23.99 50.55,26.04 U4.6
NETJ3_5: length 9.1
  BOTTOM w0.152: R5.1 38.49,8.51 37.72,8.51 37.21,8 37.21,6.6 37.85,5.97 39.88,5.97 40.77,5.08
  BOTTOM w0.305: 40.77,5.08 41.91,3.94 J3.5
NETJ3_9: length 8.9
  BOTTOM w0.152: R10.1 44.44,8 44.7,8 45.59,7.11 45.59,5.33 45.91,5.02
  BOTTOM w0.305: J3.11 J3.9 46.99,3.94 45.91,5.02
NETJ3_13: length 2.8
  TOP w0.305: R11.2 50.67,5.53 J3.13
NETJ3_14: length 6.9
  TOP w0.305: J3.14 51.05,2.6 51.05,4.45 50.29,5.21 49.28,5.21 48.39,6.1 R9.2
NETR12_2: length 3
  TOP w0.254: 43.21,10.03 44.6,10.03 v1(44.86,9.78)
  BOTTOM w0.254: v1(44.86,9.78) 45.64,10.57 R12.2
NETR17_2: length 3
  TOP w0.254: U11.2 49.94,8.76 v1(50.16,8.53)
  BOTTOM w0.254: v1(50.16,8.53) 49.58,7.95 R17.2
NETR26_2: length 3.2
  TOP w0.508: R26.2 v1(48.26,20.95)
  BOTTOM w0.635: U4.8 v1(48.26,20.95)
NETR32_1: length 2
  TOP w0.254: R36.1 R32.1
NETR34_1: length 2
  BOTTOM w0.381: R34.1 R35.2
NETR37_1: length 2
  BOTTOM w0.381: R37.1 R38.2
NETR43_2: length 3.1
  TOP w0.203: U1.54 35.36,8.07 v1(35.94,7.49)
  BOTTOM w0.203: R43.2 34.92,6.48 v1(35.94,7.49)
NETR48_1: length 2
  TOP w0.254: R49.1 R48.1
NETR50_1: length 2
  TOP w0.254: R55.1 R50.1
NETR53_1: length 2
  TOP w0.254: R53.1 R54.2
NETR65_2: length 2.8
  TOP w0.203: U1.55 35.62,8.57 v1(35.94,8.26)
  BOTTOM w0.203: v1(35.94,8.26) 35.31,7.62 R65.2
NETR71_2: length 3.4
  TOP w0.305: v1(44.83,14.73) 44.45,15.11 43.21,15.11
  BOTTOM w0.254: v1(44.83,14.73) 44.83,14.99 43.94,15.88 R71.2
NETR72_2: length 3.1
  TOP w0.254: U11.6 v1(50.16,13.84)
  BOTTOM w0.254: v1(50.16,13.84) 50.04,13.84 49.15,14.73 R72.2
NETR75_2: length 2.7
  TOP w0.381: U11.10 v1(44.83,12.57)
  BOTTOM w0.381: v1(44.83,12.57) 44.7,12.45 R75.2
NETR77_2: length 2.7
  TOP w0.254: U11.4 v1(50.16,11.3)
  BOTTOM w0.305: R77.2 v1(50.16,11.3)
NETR88_1: length 2.6
  TOP w0.305: U1.10 18.18,14.07 17.91,14.35 17.91,14.61
  TOP w0.381: 17.91,14.61 17.27,15.24 R88.1
NETR97_1: length 3.9
  TOP w0.305: U1.17 18.19,10.57 17.98,10.36 17.98,10.23
  TOP w0.508: R97.1 17.53,8.38 17.91,8.76 17.91,10.16 17.98,10.23
NETR100_1: length 3
  TOP w0.254: v1(20.95,9.91) 20.62,9.57 U1.19
  BOTTOM w0.152: R100.1 20.45,9.41 v1(20.95,9.91)
NETR108_1: length 3.3
  TOP w0.203: v1(36.2,12.78) 36.12,12.78 35.82,13.07 U1.64
  BOTTOM w0.203: v1(36.2,12.78) 36.2,12.82 35.68,13.34 R108.1
NETR109_1: length 2.6
  TOP w0.203: v1(35.94,9.02) 35.89,9.07 U1.56
  BOTTOM w0.203: v1(35.94,9.02) 35.69,8.76 R109.1
NETT1_2: length 1.9
  BOTTOM w0.508: T1.2 T2.1
NETT1_3: length 1.9
  BOTTOM w0.508: T1.3 T2.4
NETU9_6: length 3.9
  BOTTOM w0.508: U9.7 9.14,12.57 9.5,12.93 10.05,12.93 10.41,12.57 U9.6
PWM-1A: length 13.1
  GND03 w0.254: J2.2 36.32,23.5 38.65,21.17 38.65,16.75 39.14,16.26 41.53,16.26 v1(41.91,15.88)
  BOTTOM w0.203: R71.1 v1(41.91,15.88)
PWM-1AA: length 17.6
  TOP w0.254: U1.79 31.3,19.12 31.88,18.54 32.77,18.54 v1(33.27,19.05)
  BOTTOM w0.254: R73.1 41.78,14.73 41.4,14.35 37.47,14.35 36.96,14.86 35.43,14.86 34.92,15.37 34.92,17.78 33.66,19.05 v1(33.27,19.05) 33.27,19.8 R80.2
PWM-1B: length 17.4
  GND03 w0.254: J2.4 34.42,21.97 36.42,21.97 37.72,20.67 37.72,15.68 40.95,12.45 v1(41.78,12.45)
  BOTTOM w0.254: R75.1 v1(41.78,12.45)
PWM-1BB: length 19.5
  TOP w0.254: v1(32.26,19.05) 31.8,19.51 U1.78
  BOTTOM w0.254: R81.2 32.12,19.18 v1(32.26,19.05) 32.64,18.67 32.64,16 34.16,14.48 36.2,14.48 36.83,13.84 40.64,13.84 41.15,13.34 41.15,11.05 42.04,10.16 R76.1
PWM-2A: length 25.5
  GND03 w0.254: v1(46.99,11.3) 45.75,11.3 45.16,11.89 41.05,11.89 40.87,12.06 40.8,12.06 37.34,15.52 37.34,15.6 37.31,15.62 37.31,20.54 36.31,21.54 33.22,21.54 31.27,23.5 J2.6
  BOTTOM w0.381: R77.1 v1(46.99,11.3)
PWM-2AA: length 35.3
  TOP w0.254: U1.97 22.3,19.31 22.68,18.92 v1(24.38,18.92) 24.89,18.41 30.1,18.41 v1(30.73,19.05)
  BOTTOM w0.254: v1(30.73,19.05) 31.31,18.48 31.69,18.48 32.13,18.03 32.13,15.81 33.85,14.1 35.81,14.1 36.45,13.46 40.39,13.46 40.64,13.21 40.64,10.92 42.16,9.4 44.37,9.4 44.75,9.02 R78.1
  BOTTOM w0.508: v1(24.38,18.92) 24.38,19.08 23.78,19.68 R82.2
PWM-2B: length 32.3
  BOTTOM w0.254: 27.81,23.5 28.96,24.64 28.96,26.8 29.59,27.43 42.16,27.43 43.18,26.42 43.18,22.73 44.32,21.59 44.32,18.3 R72.1
PWM-2BB: length 37.3
  TOP w0.254: U1.84 28.8,21.24 v1(28.45,21.59) 27.89,22.15 26.23,22.15 R83.2
  BOTTOM w0.254: v1(28.45,21.59) 29.08,22.23 36.2,22.23 38.18,24.21 38.18,25.98 39.12,26.92 42.13,26.92 42.8,26.26 42.8,22.58 43.94,21.43 43.94,18.14 47.02,15.06 47.02,14.25 47.68,13.59 R74.1
PWM-3A: length 32.9
  GND03 w0.254: J2.5 31.5,27.18 33.37,27.18 34.04,26.51 34.04,25.37 34.69,24.71 35.86,24.71 41.26,19.31 41.26,19.2 41,18.94 40.59,18.94 40.3,18.65 40.3,18.24 40.59,17.95 41,17.95 41.26,17.68 41.26,17.23 43.61,14.88 43.64,14.88 44.42,14.11 46.32,14.11 47.7,12.73 47.7,8.74 47.19,8.23 v1(46.99,8.23)
  BOTTOM w0.254: R17.1 47.24,7.95 46.99,8.2 v1(46.99,8.23)
PWM-3AA: length 8.4
  TOP w0.254: 34.16,22.23 32.89,22.23 32.3,21.63 U1.77
  TOP w0.381: 34.16,22.23 36.07,22.23 36.83,22.99 36.86,22.99 36.89,23.01 R18.1 37.65,24.08 R19.2
PWM-3B: length 27.3
  GND03 w0.254: v1(45.64,12.57) 45.64,12.88 45.44,13.08 43.99,13.08 41.27,15.8 38.99,15.8 38.2,16.59 38.2,20.73 36.58,22.35 34.96,22.35 34.29,23.02 34.29,23.77 33.17,24.89 28.96,24.89 27.81,26.04
  BOTTOM w0.254: R12.1 v1(45.64,12.57)
PWM-3BB: length 6.8
  TOP w0.254: R16.1 R20.2 36.6,20.95 36.23,21.33 33.01,21.33
  TOP w0.305: 33.01,21.33 32.8,21.11 U1.76
REF1.65: length 13.2
  BOTTOM w0.381: R33.2 C45.1 1.52,9.64 1.52,4.57 2.03,4.06 4.45,4.06 4.83,3.68 U3.2 U3.1
RELAY: length 43.2
  TOP w0.152: v1(41.78,8.51) 41.78,6.99 41.02,6.22 41.02,5.46 40.64,5.08 36.45,5.08 35.81,5.71 35.81,6.35 35.59,6.57 U1.51
  GND03 w0.254: v1(41.78,8.51) 42.29,9.02 45.47,9.02 46.88,7.61 47.24,7.61 48.08,8.45 48.08,12.89 45.7,15.27 43.76,15.27 41.64,17.39 41.64,19.47 37.49,23.62 37.49,25.35 36.91,25.93 35.53,25.93 J2.1
SCL: length 8.3
  TOP w0.152: R94.1 38.35,6.74 U12.6 38.35,9.77 37.68,10.44 36.88,10.44 36.68,10.24 35.84,10.24 35.53,10.54 34.55,10.54 U1.59
SDA: length 7.7
  TOP w0.152: U1.58 35.52,10.07 35.64,9.96 36.8,9.96 37,10.16 37.57,10.16 37.72,10.01 37.72,9.4 37.08,8.76 U12.5 37.08,6.99 36.71,6.61 R93.1
TCK_P: length 10.5
  TOP w0.152: U1.60 35.4,11.07 35.95,10.52 36.56,10.52 36.84,10.79 38.48,10.79 v1(38.99,11.3)
  BOTTOM w0.152: R10.2 42.68,8.76 42.29,8.76 40.2,10.86 40.2,11.25 R8.1 39.62,11.56 39.24,11.56 v1(38.99,11.3)
TDI_P: length 12.9
  TOP w0.152: U1.63 35.69,12.57 36.19,12.07 v1(36.19,12.04)
  BOTTOM w0.152: 38.35,4.95 36.73,6.58 36.73,11.4 36.2,11.94 36.2,12.04 v1(36.19,12.04)
  BOTTOM w0.203: v1(36.19,12.04) 36.09,12.04 35.94,12.19 R4.1
  BOTTOM w0.305: J3.3 39.37,3.94 38.35,4.95
TDO_P: length 16.5
  TOP w0.152: U1.61 35.29,11.57 36.07,10.79 36.45,10.79 36.96,11.3 v1(37.21,11.3)
  BOTTOM w0.152: v1(37.21,11.3) 37.6,11.69 R6.1 38.23,11.09 38.48,10.83 39.71,10.83 40.89,9.65 40.89,7.87 41.4,7.37 41.4,5.59 41.91,5.08 43.05,5.08 43.43,4.7
  BOTTOM w0.305: 43.43,4.7 44.2,3.94 J3.7
TMS_P: length 11.9
  TOP w0.152: v1(36.2,11.3) 35.43,12.07 U1.62
  BOTTOM w0.152: R2.1 35.04,9.78 35.94,9.78 36.45,9.27 36.45,5.33
  BOTTOM w0.203: v1(36.2,11.3) 35.17,11.3 R107.1 R2.1
  BOTTOM w0.305: 36.45,5.33 36.45,4.51 J3.1
TRST_P: length 5.9
  BOTTOM w0.152: R1.2 C2.2 34.04,2.91 35.05,1.91 36.51,1.91 J3.2
VA+5V: length 6.4
  TOP w0.508: R41.2 v1(6.99,1.78)
  BOTTOM w0.381: v1(6.99,7.23) R25.2 R42.2
  BOTTOM w0.66: 7.62,22.43 J1.8
  BOTTOM w0.762: 7.37,21.72 7.37,23.24 J1.8
  vias: v1(6.99,19.43) v1(6.99,18.8) v1(6.99,18.06) v1(28.7,3.17) v1(29.59,3.17)
VAC: length 11.9
  TOP w0.508: M1.1 12.83,10.15 13.22,10.54 C48.1 R86.2
  BOTTOM w0.508: R40.1 10.03,4.95 10.67,4.32 11.64,4.32 D14.3 11.94,5.08 12.83,5.97 M1.1
VDC_L: length 2.2
  TOP w0.508: R45.2 13.97,5.96 14.11,6.1 C31.1 14.99,6.1 14.99,6.1 R27.2
VDC_U: length 13.4
  TOP w0.508: R46.2 C34.1 10.42,2.15 10.93,2.66 12.18,2.66 13.08,3.56 13.85,3.56 14.61,2.79 D13.3 18.12,3.17 R89.2
VL: length 15.5
  BOTTOM w0.381: R34.2 0.76,22.36 0.76,26.88 2.08,28.19 5.46,28.19 J1.7
VN: length 15.2
  BOTTOM w0.381: R37.2 3.68,21.72 2.16,21.72 1.27,22.61 1.27,26.67 2.29,27.69 5.25,27.69 5.74,27.2 5.74,26.69 J1.9
WP: length 7.4
  TOP w0.127: 35.31,9.57 U1.57
  TOP w0.152: v1(39,10.36) 39,10.28 39.12,10.16 39.12,9.4 39.62,8.89 U12.7 ; 35.31,9.57 37.13,9.57 v1(37.27,9.72)
  BOTTOM w0.152: v1(37.27,9.72) 37.34,9.65 R95.1 38.86,9.9 38.86,10.23 v1(39,10.36)
XRS: length 6.6
  TOP w0.203: R7.1 C5.1 19.94,19.18 20.19,18.92 20.19,18.54 19.72,18.07 U1.2

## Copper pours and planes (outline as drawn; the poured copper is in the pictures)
AGND on TOP: 26.42,0.51 26.29,0.64 26.29,2.03 26.42,2.16 28.32,2.16 28.45,2.03 28.45,0.64 28.32,0.51
AGND on BOTTOM: 21.46,19.81 20.07,19.81 19.94,19.68 18.29,19.68 18.03,19.94 17.4,19.94 17.27,19.81 13.34,19.81 12.32,18.8 12.32,17.4 18.92,17.4 20.57,19.05 21.46,19.05
AGND on BOTTOM: 25.78,7.24 25.78,13.97 25.65,14.1 21.59,14.1 21.46,13.97 21.46,7.37 21.59,7.24 22.1,7.24 22.23,7.37 22.23,8.13 22.35,8.26 23.62,8.26 23.75,8.13 23.75,7.37 24,7.11 25.65,7.11
AGND on BOTTOM: 0.64,28.83 0.64,29.34 0.76,29.46 17.02,29.46 17.14,29.34 17.14,27.94 17.4,27.69 19.3,27.69 19.43,27.56 19.43,27.05 17.53,25.15 16.76,25.15 16.51,25.4 16.51,26.92 16.13,27.3 6.99,27.3 5.59,28.7 0.76,28.7
AGND on POWER02: 0.51,0.51 0.51,23.5 0.51,25.78 0.51,29.46 18.92,29.46 18.92,19.18 18.29,18.54 18.29,14.99 19.18,14.1 25.65,14.1 25.78,13.97 25.78,3.94 28.57,1.14 28.57,0.64 28.45,0.51
AGND on GND03: 21.08,14.1 25.65,14.1 25.78,13.97 25.78,7.11 25.65,6.99 23.11,6.99 20.95,9.14 20.95,13.97
AGND on GND03: 16.13,29.46 16.26,29.34 16.26,28.83 16.13,28.7 3.3,28.7 1.14,26.54 1.14,20.57 2.03,19.68 7.75,19.68 7.75,11.68 12.45,6.99 15.88,6.99 20.95,1.91 27.81,1.91 28.57,1.14 28.57,0.64 28.45,0.51 0.64,0.51 0.51,0.64 0.51,29.34 0.64,29.46
DGND on TOP: 30.35,0.51 30.23,0.64 30.23,0.89 30.35,1.02 34.04,1.02 34.16,1.14 34.16,2.03 34.29,2.16 35.18,2.16 35.31,2.29 35.31,2.67 35.43,2.79 35.81,2.79 35.94,2.67 35.94,0.64 35.81,0.51
DGND on TOP: 22.23,26.04 22.23,27.18 22.35,27.3 24,27.3 24.13,27.18 24.13,26.04 24,25.91 22.35,25.91
DGND on BOTTOM: 20.19,16.26 20.19,15.11 20.45,14.86 26.04,14.86 26.54,14.35 26.54,5.84 26.67,5.71 27.43,5.71 27.56,5.59 27.56,4.83 27.69,4.7 29.84,4.7 29.97,4.83 29.97,6.22 30.35,6.6 31.5,6.6 32.13,7.24 32.13,15.24 31.75,15.62 31.75,17.78 31.62,17.91 24,17.91 23.88,18.03 23.88,18.92 23.75,19.05 22.99,19.05 22.86,19.18 22.86,20.32 22.99,20.45 24.51,20.45 26.29,22.23 26.92,22.23 27.18,21.97 27.18,21.34 27.3,21.21 27.81,21.21 27.94,21.34 27.94,22.23 27.18,22.99 22.1,22.99 21.97,22.86 21.97,16.76 21.84,16.64 21.34,16.64 21.21,16.51 20.45,16.51
DGND on BOTTOM: 38.48,28.07 38.48,29.34 38.61,29.46 43.56,29.46 43.69,29.34 43.69,28.07 43.56,27.94 38.61,27.94
DGND on BOTTOM: 39.12,18.92 39.24,19.05 41.27,19.05 41.4,18.92 41.4,14.99 41.27,14.86 39.24,14.86 39.12,14.99
DGND on BOTTOM: 21.59,27.81 21.72,27.94 25.02,27.94 25.15,27.81 25.15,26.42 24.51,25.78 21.97,25.78 21.84,25.65 21.34,25.65 21.34,26.16 21.59,26.42
DGND on POWER02: 30.23,0.64 26.54,4.32 26.54,14.35 26.04,14.86 19.43,14.86 19.05,15.24 19.05,18.03 19.68,18.67 19.68,24.26 20.32,24.89 20.32,29.34 20.45,29.46 43.56,29.46 43.69,29.34 43.69,18.41 46.48,15.62 49.91,15.62 50.67,14.86 50.67,0.89 50.42,0.64
DGND on GND03: 26.54,13.97 26.67,14.1 29.46,14.1 29.59,13.97 29.59,5.84 29.46,5.71 26.67,5.71 26.54,5.84
DGND on GND03: 29.84,1.02 30.35,0.51 35.81,0.51 35.94,0.64 50.42,0.64 50.67,0.89 50.67,14.86 49.91,15.62 47.62,15.62 44.64,18.61 44.64,21.65 43.69,22.61 43.69,29.34 43.56,29.46 20.45,29.46 20.32,29.34 20.32,28.7 20.45,28.57 36.07,28.57 39.12,25.53 39.12,24.77 39.37,24.51 39.37,21.97 47.88,13.46 47.88,6.35 44.83,6.35 43.31,4.83 36.58,4.83 34.92,3.17 31.11,3.17 29.84,1.91
A_1.2V on BOTTOM (solid shape): 21.21,29.34 21.21,28.32 19.81,28.32 19.56,28.07 17.65,28.07 17.53,28.19 17.53,29.34 17.65,29.46 21.08,29.46
A_1.2V on GND03: 17.14,27.3 17.14,29.08 17.53,29.46 19.3,29.46 19.43,29.34 19.43,28.7 17.91,27.18 17.27,27.18
A_3.3V on BOTTOM (solid shape): 21.34,22.61 21.34,21.34 19.94,19.94 18.41,19.94 18.16,20.19 17.65,20.19 17.53,20.32 17.53,21.84 17.91,22.23 18.67,22.23 19.18,22.73 21.21,22.73
A_3.3V on BOTTOM: 16.51,3.05 18.03,1.52 21.59,1.52 21.59,3.3 23.37,5.08 24.13,5.08 24.77,5.71 24.77,6.6 24.51,6.86 21.46,6.86 21.08,7.24 21.08,8.13 20.45,8.76 19.68,8.76 19.56,8.89 19.56,12.32 19.68,12.45 20.45,12.45 20.45,13.84 18.03,16.26 16.64,16.26 16.51,16.13
A_3.3V on GND03: 4.57,24.26 5.08,23.75 16,23.75 16.38,23.37 16.64,23.37 18.16,21.84 18.16,15.24 19.43,13.97 20.32,13.97 20.45,13.84 20.45,13.46 20.07,13.08 12.19,13.08 10.03,15.24 10.03,18.54 8.51,20.07 2.54,20.07 1.65,20.95 1.65,23.88 2.03,24.26
CAN_GND on BOTTOM: 57.53,21.97 57.53,18.54 57.66,18.41 58.8,18.41 58.93,18.29 58.93,16.38 59.05,16.26 59.44,16.26 59.69,16.51 59.69,26.8 59.56,26.92 58.55,26.92 58.42,26.8 58.42,22.86
CAN_GND on POWER02: 46.86,29.46 59.31,29.46 59.44,29.34 59.44,0.64 59.31,0.51 54.99,0.51 54.86,0.64 54.86,4.83 54.86,6.1 53.72,7.24 53.72,17.53 51.18,20.07 47.88,20.07 46.74,21.21 46.74,29.34 ; 1 cut-out
CAN_GND on GND03: 47.88,20.07 46.74,21.21 46.74,29.34 46.86,29.46 59.31,29.46 59.44,29.34 59.44,0.64 59.31,0.51 54.99,0.51 54.86,0.64 54.86,4.83 54.86,6.1 53.72,7.24 53.72,17.53 51.18,20.07 ; 2 cut-outs
D_1.2V on BOTTOM: 20.95,26.42 21.21,26.67 21.21,27.56 21.08,27.69 19.94,27.69 19.81,27.56 19.81,26.8 19.05,26.04 19.05,24.89 19.18,24.77 19.81,24.77 20.32,25.27 20.7,25.27 20.95,25.53
D_1.2V on GND03: 19.68,27.05 20.7,27.05 20.83,26.92 20.83,20.7 19.81,19.68 19.81,17.53 20.07,17.27 21.08,17.27 23.5,19.68 31.5,19.68 31.75,19.43 31.75,18.8 32,18.54 33.15,18.54 33.4,18.29 33.4,7.24 32.89,6.73 31.37,6.73 30.99,6.35 30.99,5.97 30.86,5.84 30.48,5.84 29.97,6.35 29.97,14.1 29.59,14.48 19.56,14.48 18.54,15.49 18.54,25.91
D_3.3V on BOTTOM (solid shape): 23.24,25.27 23.24,24.38 23.11,24.26 22.73,24.26 22.61,24.13 22.61,23.37 22.48,23.24 21.84,23.24 21.59,23.5 20.07,23.5 19.94,23.62 19.94,24.38 20.19,24.64 20.83,24.64 21.46,25.27 22.1,25.27 22.23,25.4 23.11,25.4
D_3.3V on BOTTOM: 38.34,18.91 37.47,18.03 37.47,15.37 35.56,15.37 35.43,15.49 35.43,17.78 36.83,19.18 36.83,22.23 38.48,23.88 38.99,23.88 38.99,23.11 38.1,22.23 38.1,21.21 38.23,21.08 39.24,21.08 39.37,20.95 39.37,20.45 39.5,20.32 42.93,20.32 43.05,20.19 43.05,19.05 42.91,18.91
D_3.3V on GND03: 31.5,4.32 31.37,4.45 31.37,6.22 31.5,6.35 32.77,6.35 33.27,6.35 33.78,6.86 33.78,18.67 33.02,19.43 32.38,19.43 31.75,20.07 23.11,20.07 20.83,17.78 20.32,17.78 20.19,17.91 20.19,19.56 21.21,20.57 21.21,25.65 21.34,25.78 24.26,25.78 24.51,26.04 24.51,26.67 25.15,27.3 26.54,27.3 26.67,27.18 26.67,22.99 27.11,22.54 33.34,22.54 34.29,21.59 36.83,21.59 36.96,21.46 36.96,14.48 40.26,11.18 40.26,9.14 41.4,8 42.29,8 43.18,8.89 46.35,8.89 47.37,7.87 47.37,6.86 47.24,6.73 45.34,6.73 44.96,7.11 44.2,7.11 42.93,5.84 36.2,5.84 34.67,4.32
VA+5V on TOP: 28.83,1.52 28.83,2.29 28.45,2.67 28.45,3.3 28.57,3.43 30.86,3.43 30.99,3.3 30.99,1.4 28.96,1.4
VA+5V on BOTTOM: 6.73,17.91 6.86,17.78 7.24,17.78 7.37,17.91 7.37,18.29 7.62,18.54 7.75,18.54 7.87,18.67 7.87,21.59 8.51,22.23 8.51,23.88 8.13,24.26 6.99,24.26 6.73,24
VA+5V on GND03: 14.99,8.89 13.34,8.89 11.18,6.73 11.18,4.7 8,1.52 6.73,1.52 6.6,1.65 6.6,7.11 7.81,8.32 7.81,10.86 6.6,12.06 6.6,19.56 6.73,19.68 8.26,19.68 9.65,18.29 9.65,14.73 11.68,12.7 17.14,12.7 24.77,5.08 29.84,5.08 29.97,4.95 29.97,2.79 29.72,2.54 21.34,2.54
VD+5V on TOP (solid shape): 33.91,1.4 33.78,1.27 31.88,1.27 31.75,1.4 31.75,3.05 31.88,3.17 33.91,3.17

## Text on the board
BOTTOM: ARTWORK BOTTOM
Board Geometry/Soldermask Bottom: SOLDERMASK BOTTOM
Package Geometry/Pastemask Bottom: PASTEMASK BOTTOM
Ref Des/Silkscreen Bottom: A | SILKSCREEN BOTTOM
TOP: ARTWORK TOP
Board Geometry/Soldermask Top: SOLDERMASK TOP
Package Geometry/Pastemask Top: PASTEMASK TOP
Ref Des/Silkscreen Top: A | D | C | B | CRD33FF12N-K_CNTL_V1_0 | 2025W11 | SILKSCREEN TOP
POWER02: POWER PLANE02
GND03: GROUND PLANE03
